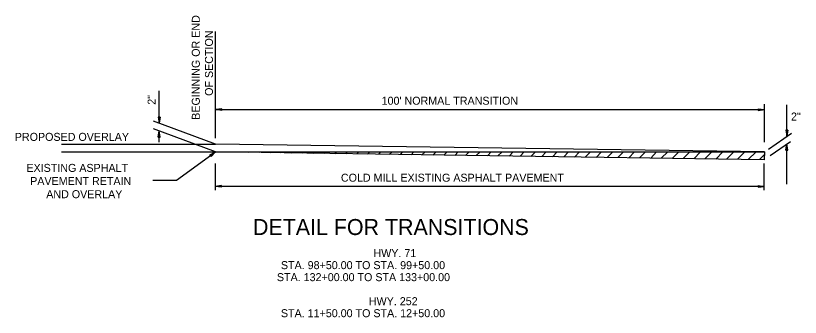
# Model space of a CAD drawing. Extents: x 634177 to 635904, y 289936 to 290970.
# Drawn here: x 635632.8 to 635691.6, y 290936.9 to 290959.5 of the extents above; entities that cross this region are included whole.
import ezdxf

# ---------------------------------------------------------------- set-up
doc = ezdxf.new("R2010")
doc.units = 0
doc.layers.add('Default', color=7, linetype='Continuous')

msp = doc.modelspace()

# ---------------------------------------------------------------- linework, layer by layer
at = {"layer": 'Default'}
for p, q in [((635647.733, 290950.312), (635647.733, 290958.298)), ((635643.513, 290951.446), (635643.513, 290953.845)), ((635688.889, 290950.002), (635688.889, 290952.844)), ((635690.575, 290950.445), (635690.575, 290952.799)), ((635648.2, 290952.512), (635647.733, 290952.445)), ((635647.733, 290952.445), (635688.889, 290952.445)), ((635648.2, 290952.379), (635647.733, 290952.445)), ((635648.2, 290952.49), (635647.801, 290952.445)), ((635648.2, 290952.379), (635647.801, 290952.445)), ((635648.2, 290952.49), (635647.889, 290952.445)), ((635648.2, 290952.401), (635647.889, 290952.445)), ((635648.2, 290952.467), (635647.978, 290952.445)), ((635648.2, 290952.401), (635647.978, 290952.445)), ((635648.2, 290952.467), (635648.045, 290952.445)), ((635648.2, 290952.424), (635648.045, 290952.445)), ((635648.2, 290952.445), (635648.133, 290952.445)), ((635648.2, 290952.424), (635648.133, 290952.445)), ((635648.2, 290952.379), (635648.2, 290952.512)), ((635688.421, 290952.512), (635688.889, 290952.445)), ((635688.421, 290952.512), (635688.421, 290952.379)), ((635688.421, 290952.49), (635688.733, 290952.445)), ((635688.421, 290952.49), (635688.798, 290952.445)), ((635688.421, 290952.467), (635688.577, 290952.445)), ((635688.421, 290952.467), (635688.645, 290952.445)), ((635688.421, 290952.379), (635688.889, 290952.445)), ((635688.421, 290952.424), (635688.577, 290952.445)), ((635688.421, 290952.401), (635688.733, 290952.445)), ((635688.421, 290952.379), (635688.798, 290952.445)), ((635688.421, 290952.401), (635688.645, 290952.445)), ((635688.421, 290952.424), (635688.489, 290952.445)), ((635688.421, 290952.445), (635688.489, 290952.445)), ((635643.446, 290951.891), (635643.513, 290951.446)), ((635643.446, 290951.891), (635643.513, 290951.512)), ((635643.58, 290951.891), (635643.446, 290951.891)), ((635643.47, 290951.891), (635643.513, 290951.602)), ((635643.47, 290951.891), (635643.513, 290951.667)), ((635643.491, 290951.891), (635643.513, 290951.757)), ((635643.491, 290951.891), (635643.513, 290951.823)), ((635643.58, 290951.891), (635643.513, 290951.446)), ((635643.535, 290951.891), (635643.513, 290951.757)), ((635643.558, 290951.891), (635643.513, 290951.602)), ((635643.558, 290951.891), (635643.513, 290951.512)), ((635643.535, 290951.891), (635643.513, 290951.667)), ((635643.513, 290951.891), (635643.513, 290951.823)), ((635647.733, 290949.846), (635643.092, 290951.579)), ((635647.733, 290949.27), (635643.092, 290951.001)), ((635643.446, 290950.379), (635643.513, 290950.845)), ((635643.446, 290950.379), (635643.513, 290950.779)), ((635643.47, 290950.379), (635643.513, 290950.691)), ((635643.47, 290950.379), (635643.513, 290950.625)), ((635643.491, 290950.379), (635643.513, 290950.535)), ((635643.491, 290950.379), (635643.513, 290950.445)), ((635643.58, 290950.379), (635643.513, 290950.845)), ((635643.513, 290950.002), (635643.513, 290950.845)), ((635643.558, 290950.379), (635643.513, 290950.779)), ((635643.558, 290950.379), (635643.513, 290950.691)), ((635643.535, 290950.379), (635643.513, 290950.625)), ((635643.535, 290950.379), (635643.513, 290950.535)), ((635643.513, 290950.379), (635643.513, 290950.445)), ((635689.199, 290949.492), (635690.931, 290950.691)), ((635690.509, 290950.912), (635690.575, 290950.445)), ((635690.642, 290950.912), (635690.509, 290950.912)), ((635690.532, 290950.912), (635690.575, 290950.601)), ((635690.532, 290950.912), (635690.575, 290950.535)), ((635690.553, 290950.912), (635690.575, 290950.757)), ((635690.553, 290950.912), (635690.575, 290950.691)), ((635690.642, 290950.912), (635690.575, 290950.445)), ((635690.597, 290950.912), (635690.575, 290950.757)), ((635690.621, 290950.912), (635690.575, 290950.601)), ((635690.642, 290950.912), (635690.575, 290950.535)), ((635690.621, 290950.912), (635690.575, 290950.691)), ((635690.575, 290950.912), (635690.575, 290950.845)), ((635690.597, 290950.912), (635690.575, 290950.845)), ((635636.185, 290949.846), (635647.733, 290949.846)), ((635643.446, 290950.379), (635643.58, 290950.379)), ((635688.889, 290949.27), (635647.733, 290949.846)), ((635689.332, 290949.003), (635690.843, 290950.068)), ((635690.509, 290949.402), (635690.575, 290949.869)), ((635690.575, 290946.848), (635690.575, 290949.869)), ((635690.642, 290949.402), (635690.575, 290949.869)), ((635636.185, 290949.269), (635688.889, 290949.269)), ((635644.803, 290947.16), (635647.733, 290949.27)), ((635647.311, 290949.046), (635647.733, 290949.27)), ((635647.4, 290948.936), (635647.733, 290949.27)), ((635688.866, 290948.691), (635647.733, 290949.27)), ((635649.353, 290949.246), (635649.377, 290949.27)), ((635650.164, 290949.236), (635650.198, 290949.27)), ((635650.975, 290949.224), (635651.042, 290949.27)), ((635651.806, 290949.212), (635651.865, 290949.27)), ((635652.619, 290949.201), (635652.686, 290949.27)), ((635653.429, 290949.189), (635653.508, 290949.27)), ((635654.24, 290949.178), (635654.329, 290949.27)), ((635655.069, 290949.166), (635655.173, 290949.27)), ((635655.88, 290949.155), (635655.996, 290949.27)), ((635656.713, 290949.143), (635656.818, 290949.27)), ((635657.502, 290949.132), (635657.639, 290949.27)), ((635658.335, 290949.12), (635658.483, 290949.27)), ((635659.144, 290949.109), (635659.306, 290949.27)), ((635659.975, 290949.097), (635660.128, 290949.27)), ((635660.764, 290949.086), (635660.971, 290949.27)), ((635661.599, 290949.075), (635661.793, 290949.27)), ((635662.409, 290949.063), (635662.614, 290949.27)), ((635663.219, 290949.05), (635663.437, 290949.268)), ((635664.029, 290949.04), (635664.279, 290949.27)), ((635664.862, 290949.029), (635665.101, 290949.27)), ((635665.672, 290949.017), (635665.923, 290949.27)), ((635666.482, 290949.006), (635666.744, 290949.27)), ((635667.291, 290948.995), (635667.588, 290949.27)), ((635668.124, 290948.983), (635668.41, 290949.27)), ((635668.911, 290948.971), (635669.232, 290949.27)), ((635669.746, 290948.96), (635670.054, 290949.27)), ((635670.577, 290948.948), (635670.876, 290949.27)), ((635671.387, 290948.936), (635671.719, 290949.27)), ((635672.198, 290948.925), (635672.541, 290949.27)), ((635673.009, 290948.914), (635673.363, 290949.27)), ((635673.842, 290948.902), (635674.208, 290949.27)), ((635674.653, 290948.891), (635675.029, 290949.27)), ((635675.462, 290948.879), (635675.851, 290949.27)), ((635676.272, 290948.868), (635676.672, 290949.27)), ((635677.104, 290948.856), (635677.516, 290949.27)), ((635677.894, 290948.845), (635678.338, 290949.27)), ((635678.726, 290948.834), (635679.16, 290949.27)), ((635679.536, 290948.822), (635679.981, 290949.27)), ((635680.367, 290948.811), (635680.805, 290949.27)), ((635681.155, 290948.799), (635681.648, 290949.27)), ((635681.988, 290948.788), (635682.47, 290949.27)), ((635682.803, 290948.78), (635683.291, 290949.27)), ((635683.609, 290948.765), (635684.113, 290949.27)), ((635684.419, 290948.754), (635684.957, 290949.27)), ((635685.251, 290948.742), (635685.778, 290949.27)), ((635686.062, 290948.73), (635686.601, 290949.27)), ((635686.873, 290948.719), (635687.421, 290949.27)), ((635687.682, 290948.708), (635688.266, 290949.27)), ((635688.889, 290949.27), (635688.866, 290948.691)), ((635690.509, 290949.402), (635690.642, 290949.402)), ((635690.532, 290949.402), (635690.575, 290949.802)), ((635690.532, 290949.402), (635690.575, 290949.713)), ((635690.553, 290949.402), (635690.575, 290949.646)), ((635690.553, 290949.402), (635690.575, 290949.557)), ((635690.642, 290949.402), (635690.575, 290949.802)), ((635690.621, 290949.402), (635690.575, 290949.713)), ((635690.621, 290949.402), (635690.575, 290949.646)), ((635690.597, 290949.402), (635690.575, 290949.557)), ((635690.597, 290949.402), (635690.575, 290949.492)), ((635690.575, 290949.402), (635690.575, 290949.492)), ((635647.311, 290949.046), (635647.4, 290948.936)), ((635647.334, 290949.046), (635647.667, 290949.225)), ((635647.334, 290949.046), (635647.6, 290949.18)), ((635647.334, 290949.024), (635647.532, 290949.135)), ((635647.334, 290949.024), (635647.489, 290949.092)), ((635647.356, 290949.003), (635647.422, 290949.046)), ((635647.356, 290949.003), (635647.422, 290949.046)), ((635647.378, 290948.958), (635647.6, 290949.18)), ((635647.378, 290948.981), (635647.532, 290949.135)), ((635647.378, 290948.981), (635647.489, 290949.092)), ((635647.4, 290948.958), (635647.667, 290949.225)), ((635688.515, 290948.695), (635688.88, 290949.06)), ((635647.733, 290946.403), (635647.733, 290948.402)), ((635688.866, 290946.403), (635688.866, 290948.402)), ((635643.048, 290947.16), (635644.803, 290947.16)), ((635648.179, 290946.759), (635647.733, 290946.693)), ((635648.179, 290946.759), (635647.733, 290946.693)), ((635688.866, 290946.693), (635647.733, 290946.693)), ((635648.179, 290946.626), (635647.733, 290946.693)), ((635648.179, 290946.626), (635647.733, 290946.693)), ((635648.179, 290946.759), (635647.801, 290946.693)), ((635648.179, 290946.759), (635647.801, 290946.693)), ((635648.179, 290946.648), (635647.801, 290946.693)), ((635648.179, 290946.648), (635647.801, 290946.693)), ((635648.179, 290946.738), (635647.889, 290946.693)), ((635648.179, 290946.738), (635647.889, 290946.693)), ((635648.179, 290946.648), (635647.889, 290946.693)), ((635648.179, 290946.648), (635647.889, 290946.693)), ((635648.179, 290946.738), (635647.956, 290946.693)), ((635648.179, 290946.738), (635647.956, 290946.693)), ((635648.179, 290946.671), (635647.956, 290946.693)), ((635648.179, 290946.671), (635647.956, 290946.693)), ((635648.179, 290946.714), (635648.045, 290946.693)), ((635648.179, 290946.714), (635648.045, 290946.693)), ((635648.179, 290946.671), (635648.045, 290946.693)), ((635648.179, 290946.671), (635648.045, 290946.693)), ((635648.179, 290946.714), (635648.112, 290946.693)), ((635648.179, 290946.714), (635648.112, 290946.693)), ((635648.179, 290946.693), (635648.112, 290946.693)), ((635648.179, 290946.693), (635648.112, 290946.693)), ((635648.179, 290946.626), (635648.179, 290946.759)), ((635648.179, 290946.626), (635648.179, 290946.759)), ((635688.421, 290946.759), (635688.866, 290946.693)), ((635688.421, 290946.759), (635688.798, 290946.693)), ((635688.421, 290946.759), (635688.421, 290946.626)), ((635688.421, 290946.738), (635688.71, 290946.693)), ((635688.421, 290946.738), (635688.645, 290946.693)), ((635688.421, 290946.714), (635688.556, 290946.693)), ((635688.421, 290946.714), (635688.489, 290946.693)), ((635688.421, 290946.626), (635688.866, 290946.693)), ((635688.421, 290946.671), (635688.556, 290946.693)), ((635688.421, 290946.648), (635688.71, 290946.693)), ((635688.421, 290946.648), (635688.798, 290946.693)), ((635688.421, 290946.671), (635688.645, 290946.693)), ((635688.421, 290946.693), (635688.489, 290946.693))]:
    msp.add_line(p, q, dxfattribs=at)

# ---------------------------------------------------------------- texts
for s, p in [('BEGINNING OR END', (635646.56, 290951.685)), ('OF SECTION', (635647.546, 290953.479)), ('2"', (635643.247, 290952.812))]:
    msp.add_text(s, height=0.6, rotation=90, dxfattribs=at).set_placement(p)
for s, height, p in [("100' NORMAL TRANSITION", 0.6, (635660.193, 290952.814)), ('2"', 0.6, (635690.888, 290951.629)), ('PROPOSED OVERLAY', 0.6, (635632.689, 290950.103)), ('EXISTING ASPHALT', 0.6, (635633.558, 290947.776)), ('COLD MILL EXISTING ASPHALT PAVEMENT', 0.6, (635657.14, 290947.04)), ('PAVEMENT RETAIN', 0.6, (635633.841, 290946.79)), ('AND OVERLAY', 0.6, (635635.046, 290945.804)), ('DETAIL FOR TRANSITIONS', 1.2, (635650.547, 290943.041)), ('HWY. 71', 0.6, (635659.581, 290941.384)), ('STA. 98+50.00 TO STA. 99+50.00', 0.6, (635652.641, 290940.482)), ('STA. 132+00.00 TO STA 133+00.00', 0.6, (635652.341, 290939.581)), ('HWY. 252', 0.6, (635659.237, 290937.779)), ('STA. 11+50.00 TO STA. 12+50.00', 0.6, (635652.641, 290936.878))]:
    msp.add_text(s, height=height, dxfattribs=at).set_placement(p)

doc.saveas('drawing.dxf')
